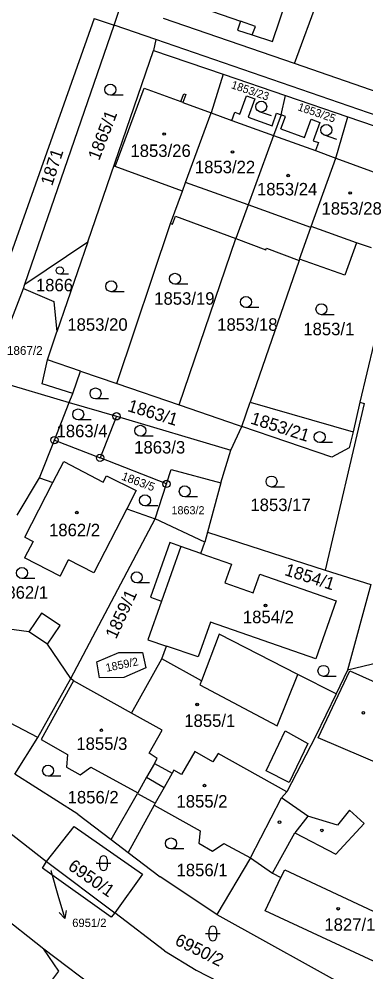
# Model space of a CAD drawing. Extents: x -593183 to -588034, y -1130415 to -1124994.
# Drawn here: x -590455.2 to -590407.9, y -1129215.7 to -1129085.7 of the extents above; entities that cross this region are included whole.
import ezdxf

# ---------------------------------------------------------------- set-up
doc = ezdxf.new("R2010")
doc.units = 0
for name, color, linetype in [('Vrstva 1', 7, 'Continuous'), ('Vrstva 16', 7, 'Continuous'), ('Vrstva 18', 7, 'Continuous'), ('Vrstva 19', 7, 'Continuous'), ('Vrstva 24', 7, 'Continuous'), ('Vrstva 25', 7, 'Continuous'), ('Vrstva 4', 7, 'Continuous')]:
    doc.layers.add(name, color=color, linetype=linetype)

msp = doc.modelspace()

# ---------------------------------------------------------------- linework, layer by layer
at = {"layer": 'Vrstva 1'}
for p, q in [((-590417.69, -1129091.82), (-590414.33, -1129082.68)), ((-590444.97, -1129085.65), (-590459.63, -1129127.02)), ((-590454.41, -1129121.9), (-590442.26, -1129086.59)), ((-590444.97, -1129085.65), (-590442.26, -1129086.59)), ((-590436.59, -1129088.54), (-590442.26, -1129086.59)), ((-590417.69, -1129091.82), (-590435.53, -1129085.66)), ((-590436.59, -1129088.54), (-590436.88, -1129090.02)), ((-590395.82, -1129102.61), (-590436.59, -1129088.54)), ((-590445.83, -1129116.11), (-590436.88, -1129090.02)), ((-590436.88, -1129090.02), (-590427.42, -1129093.26)), ((-590395.13, -1129099.59), (-590417.69, -1129091.82)), ((-590427.42, -1129093.26), (-590429.01, -1129098.55)), ((-590427.42, -1129093.26), (-590418.91, -1129096.18)), ((-590442.11, -1129105.83), (-590438.16, -1129095.16)), ((-590438.16, -1129095.16), (-590433.16, -1129097.01)), ((-590433.16, -1129097.01), (-590432.76, -1129095.93)), ((-590432.76, -1129095.93), (-590432.48, -1129096.03)), ((-590432.48, -1129096.03), (-590432.88, -1129097.12)), ((-590432.88, -1129097.12), (-590429.01, -1129098.55)), ((-590425.14, -1129098.7), (-590424.23, -1129096.2)), ((-590424.23, -1129096.2), (-590423.08, -1129096.62)), ((-590423.08, -1129096.62), (-590423.98, -1129099.12)), ((-590419.5, -1129098.81), (-590418.91, -1129096.18)), ((-590418.91, -1129096.18), (-590410.39, -1129099.1)), ((-590432.52, -1129108.04), (-590429.01, -1129098.55)), ((-590429.01, -1129098.55), (-590426.23, -1129099.56)), ((-590426.23, -1129099.56), (-590425.83, -1129098.45)), ((-590425.83, -1129098.45), (-590425.14, -1129098.7)), ((-590423.98, -1129099.12), (-590420.74, -1129100.29)), ((-590420.74, -1129100.29), (-590420.12, -1129098.58)), ((-590419.5, -1129098.81), (-590420.53, -1129101.62)), ((-590420.12, -1129098.58), (-590419.5, -1129098.81)), ((-590419.54, -1129100.73), (-590418.92, -1129099.02)), ((-590418.92, -1129099.02), (-590419.5, -1129098.81)), ((-590416.3, -1129101.9), (-590415.4, -1129099.4)), ((-590415.4, -1129099.4), (-590414.21, -1129099.83)), ((-590414.21, -1129099.83), (-590415.12, -1129102.33)), ((-590412.05, -1129104.7), (-590410.39, -1129099.1)), ((-590410.39, -1129099.1), (-590402.83, -1129101.7)), ((-590419.54, -1129100.73), (-590416.3, -1129101.9)), ((-590420.53, -1129101.62), (-590423.99, -1129111.1)), ((-590415.12, -1129102.33), (-590414.42, -1129102.58)), ((-590414.42, -1129102.58), (-590414.83, -1129103.69)), ((-590414.83, -1129103.69), (-590412.05, -1129104.7)), ((-590415.39, -1129114.03), (-590412.05, -1129104.7)), ((-590412.05, -1129104.7), (-590403.97, -1129107.67)), ((-590400.88, -1129104.55), (-590408.76, -1129137.99)), ((-590432.96, -1129109.22), (-590442.11, -1129105.83)), ((-590432.96, -1129109.22), (-590432.52, -1129108.04)), ((-590434.59, -1129113.62), (-590432.96, -1129109.22)), ((-590423.99, -1129111.1), (-590425.66, -1129115.69)), ((-590434.3, -1129113.73), (-590433.9, -1129112.64)), ((-590433.9, -1129112.64), (-590425.66, -1129115.69)), ((-590441.89, -1129135.45), (-590434.59, -1129113.62)), ((-590434.59, -1129113.62), (-590434.3, -1129113.73)), ((-590415.44, -1129114.17), (-590415.39, -1129114.03)), ((-590416.98, -1129118.47), (-590415.44, -1129114.17)), ((-590454.41, -1129121.9), (-590445.83, -1129116.11)), ((-590445.83, -1129116.11), (-590450.04, -1129128.4)), ((-590433.38, -1129138.37), (-590425.66, -1129115.69)), ((-590425.66, -1129115.69), (-590421.58, -1129117.2)), ((-590409.21, -1129116.24), (-590410.81, -1129120.68)), ((-590407.2, -1129116.96), (-590409.21, -1129116.24)), ((-590421.58, -1129117.2), (-590421.51, -1129117.01)), ((-590421.51, -1129117.01), (-590417.05, -1129118.66)), ((-590417.05, -1129118.66), (-590423.73, -1129137.98)), ((-590416.98, -1129118.47), (-590417.05, -1129118.66)), ((-590410.81, -1129120.68), (-590416.98, -1129118.47)), ((-590454.62, -1129122.47), (-590454.41, -1129121.9)), ((-590458.36, -1129132.2), (-590454.62, -1129122.47)), ((-590454.62, -1129122.47), (-590450.47, -1129124.24)), ((-590450.47, -1129124.24), (-590450.04, -1129128.4)), ((-590451.35, -1129132.21), (-590450.04, -1129128.4)), ((-590446.83, -1129133.76), (-590451.35, -1129132.21)), ((-590459.53, -1129134.72), (-590448.36, -1129138.02)), ((-590447.88, -1129136.8), (-590446.83, -1129133.76)), ((-590446.83, -1129133.76), (-590441.89, -1129135.45)), ((-590441.89, -1129135.45), (-590433.38, -1129138.37)), ((-590448.36, -1129138.02), (-590447.88, -1129136.8)), ((-590450.39, -1129143.16), (-590448.36, -1129138.02)), ((-590448.36, -1129138.02), (-590441.93, -1129139.92)), ((-590433.38, -1129138.37), (-590425.34, -1129141.13)), ((-590424.87, -1129141.29), (-590423.73, -1129137.98)), ((-590423.73, -1129137.98), (-590409.7, -1129142.02)), ((-590408.19, -1129138.18), (-590413.48, -1129160.88)), ((-590408.76, -1129137.99), (-590409.7, -1129142.02)), ((-590408.76, -1129137.99), (-590408.19, -1129138.18)), ((-590441.93, -1129139.92), (-590444.17, -1129145.58)), ((-590441.93, -1129139.92), (-590426.37, -1129144.52)), ((-590426.37, -1129144.52), (-590424.87, -1129141.29)), ((-590425.34, -1129141.13), (-590424.87, -1129141.29)), ((-590412.57, -1129145.51), (-590424.87, -1129141.29)), ((-590409.7, -1129142.02), (-590410.22, -1129144.21)), ((-590452.42, -1129148.3), (-590450.39, -1129143.16)), ((-590450.39, -1129143.16), (-590444.17, -1129145.58)), ((-590427.72, -1129148.98), (-590426.37, -1129144.52)), ((-590410.22, -1129144.21), (-590412.57, -1129145.51)), ((-590450.59, -1129148.95), (-590449.11, -1129146.08)), ((-590449.11, -1129146.08), (-590443.74, -1129148.89)), ((-590435.12, -1129149.14), (-590444.17, -1129145.58)), ((-590435.12, -1129149.14), (-590434.48, -1129147.17)), ((-590434.48, -1129147.17), (-590427.72, -1129148.98)), ((-590455.45, -1129153.42), (-590452.42, -1129148.3)), ((-590454.42, -1129156.42), (-590450.59, -1129148.95)), ((-590452.42, -1129148.3), (-590450.59, -1129148.95)), ((-590443.74, -1129148.89), (-590443.28, -1129148.02)), ((-590443.28, -1129148.02), (-590439.27, -1129150.05)), ((-590436.68, -1129153.91), (-590435.12, -1129149.14)), ((-590427.72, -1129148.98), (-590429.52, -1129155.74)), ((-590439.27, -1129150.05), (-590440.54, -1129152.53)), ((-590440.54, -1129152.53), (-590445, -1129161.25)), ((-590440.54, -1129152.53), (-590436.68, -1129153.91)), ((-590448.13, -1129175.68), (-590436.68, -1129153.91)), ((-590429.88, -1129157.09), (-590436.68, -1129153.91)), ((-590429.52, -1129155.74), (-590429.88, -1129157.09)), ((-590429.52, -1129155.74), (-590413.48, -1129160.88)), ((-590453.3, -1129157), (-590454.45, -1129159.23)), ((-590454.42, -1129156.42), (-590453.3, -1129157)), ((-590434.68, -1129157.13), (-590437.3, -1129164.59)), ((-590433.17, -1129157.65), (-590434.68, -1129157.13)), ((-590430.44, -1129158.61), (-590433.17, -1129157.65)), ((-590430.44, -1129158.61), (-590429.88, -1129157.09)), ((-590449.6, -1129161.72), (-590454.45, -1129159.23)), ((-590449.6, -1129161.72), (-590448.45, -1129159.49)), ((-590445, -1129161.25), (-590448.45, -1129159.49)), ((-590430.44, -1129158.61), (-590426.28, -1129160.07)), ((-590426.28, -1129160.07), (-590427.18, -1129162.64)), ((-590413.48, -1129160.88), (-590407.29, -1129162.87)), ((-590423.31, -1129163.99), (-590422.41, -1129161.43)), ((-590422.41, -1129161.43), (-590411.98, -1129165.08)), ((-590427.18, -1129162.64), (-590423.31, -1129163.99)), ((-590407.29, -1129162.87), (-590410.48, -1129174.52)), ((-590437.3, -1129164.59), (-590435.78, -1129165.12)), ((-590435.78, -1129165.12), (-590437.64, -1129170.4)), ((-590411.98, -1129165.08), (-590414.77, -1129173.01)), ((-590452.14, -1129166.75), (-590453.87, -1129169.33)), ((-590449.61, -1129168.43), (-590452.14, -1129166.75)), ((-590451.32, -1129171), (-590449.61, -1129168.43)), ((-590429.13, -1129167.97), (-590430.81, -1129172.74)), ((-590414.77, -1129173.01), (-590429.13, -1129167.97)), ((-590453.87, -1129169.33), (-590457.53, -1129168.79)), ((-590427.96, -1129169.64), (-590430.37, -1129175.97)), ((-590417.21, -1129175.12), (-590427.96, -1129169.64)), ((-590390.09, -1129169.62), (-590410.48, -1129174.52)), ((-590448.13, -1129175.68), (-590451.32, -1129171)), ((-590437.64, -1129170.4), (-590435.11, -1129171.27)), ((-590435.74, -1129172.97), (-590435.11, -1129171.27)), ((-590430.81, -1129172.74), (-590435.11, -1129171.27)), ((-590444.63, -1129173.4), (-590441.61, -1129172.13)), ((-590441.61, -1129172.13), (-590438.38, -1129172.13)), ((-590438.38, -1129172.13), (-590437.94, -1129174.23)), ((-590444.23, -1129175.56), (-590444.63, -1129173.4)), ((-590439.89, -1129180.4), (-590435.74, -1129172.97)), ((-590430.37, -1129175.97), (-590435.74, -1129172.97)), ((-590485.36, -1129174.1), (-590451.45, -1129200.65)), ((-590437.94, -1129174.23), (-590440.95, -1129175.53)), ((-590412.02, -1129177.76), (-590417.21, -1129175.12)), ((-590410.48, -1129174.52), (-590412.02, -1129177.76)), ((-590452.66, -1129183.71), (-590448.13, -1129175.68)), ((-590447.79, -1129176), (-590452.19, -1129183.98)), ((-590447.79, -1129176), (-590448.13, -1129175.68)), ((-590439.89, -1129180.4), (-590447.79, -1129176)), ((-590440.95, -1129175.53), (-590444.23, -1129175.56)), ((-590412.02, -1129177.76), (-590414.8, -1129183.6)), ((-590435.73, -1129182.71), (-590439.89, -1129180.4)), ((-590452.66, -1129183.71), (-590457.4, -1129181.23)), ((-590437.48, -1129185.85), (-590435.73, -1129182.71)), ((-590455.78, -1129188.72), (-590452.66, -1129183.71)), ((-590452.19, -1129183.98), (-590448.6, -1129186.02)), ((-590414.8, -1129183.6), (-590418.72, -1129191.13)), ((-590448.6, -1129186.02), (-590448.76, -1129187.76)), ((-590436.38, -1129186.56), (-590437.48, -1129185.85)), ((-590436.77, -1129187.27), (-590436.38, -1129186.56)), ((-590431.27, -1129185.64), (-590433.07, -1129188.77)), ((-590428.79, -1129187.03), (-590431.27, -1129185.64)), ((-590428.1, -1129185.91), (-590428.79, -1129187.03)), ((-590418.72, -1129191.13), (-590428.1, -1129185.91)), ((-590448.76, -1129187.76), (-590446.86, -1129188.83)), ((-590446.86, -1129188.83), (-590445.44, -1129187.77)), ((-590445.44, -1129187.77), (-590439.02, -1129191.28)), ((-590436.77, -1129187.27), (-590437.82, -1129189.14)), ((-590434.14, -1129188.17), (-590434.36, -1129188.57)), ((-590433.07, -1129188.77), (-590434.14, -1129188.17)), ((-590447.21, -1129194.16), (-590455.78, -1129188.72)), ((-590437.82, -1129189.14), (-590439.02, -1129191.28)), ((-590434.36, -1129188.57), (-590435.43, -1129190.53)), ((-590435.43, -1129190.53), (-590436.64, -1129192.68)), ((-590442.65, -1129197.64), (-590439.07, -1129191.37)), ((-590439.02, -1129191.28), (-590439.07, -1129191.37)), ((-590423.69, -1129200.15), (-590419.44, -1129191.96)), ((-590419.44, -1129191.96), (-590418.72, -1129191.13)), ((-590436.78, -1129192.94), (-590440.34, -1129199.4)), ((-590436.64, -1129192.68), (-590436.78, -1129192.94)), ((-590436.78, -1129192.94), (-590430.53, -1129196.46)), ((-590447.21, -1129194.16), (-590442.65, -1129197.64)), ((-590451.45, -1129200.65), (-590447.68, -1129195.84)), ((-590447.68, -1129195.84), (-590438.41, -1129202.37)), ((-590430.53, -1129196.46), (-590430.69, -1129198.13)), ((-590451.81, -1129212.59), (-590470.99, -1129197.54)), ((-590442.65, -1129197.64), (-590440.34, -1129199.4)), ((-590430.69, -1129198.13), (-590428.86, -1129199.21)), ((-590428.86, -1129199.21), (-590427.3, -1129198.18)), ((-590427.3, -1129198.18), (-590423.69, -1129200.15)), ((-590440.34, -1129199.4), (-590435.98, -1129202.73)), ((-590452.03, -1129201.54), (-590451.45, -1129200.65)), ((-590451.45, -1129200.65), (-590442.17, -1129207.63)), ((-590423.69, -1129200.15), (-590428.24, -1129207.87)), ((-590442.65, -1129208.24), (-590452.03, -1129201.54)), ((-590438.41, -1129202.37), (-590442.17, -1129207.63)), ((-590428.24, -1129207.87), (-590435.98, -1129202.73)), ((-590442.17, -1129207.63), (-590442.65, -1129208.24)), ((-590435.37, -1129212.83), (-590442.17, -1129207.63)), ((-590428.24, -1129207.87), (-590403.83, -1129221.39)), ((-590449.79, -1129215.59), (-590451.81, -1129212.59)), ((-590437.47, -1129223.43), (-590451.81, -1129212.59)), ((-590435.37, -1129212.83), (-590431.08, -1129215.43)), ((-590431.08, -1129215.43), (-590412.29, -1129225.07)), ((-590452.4, -1129219.06), (-590449.79, -1129215.59))]:
    msp.add_line(p, q, dxfattribs=at)
at = {"layer": 'Vrstva 16'}
msp.add_line((-590450.89, -1129201.85), (-590449.81, -1129205.54), dxfattribs=at)
at = {"layer": 'Vrstva 24'}
for centre, radius in [((-590441.93, -1129139.92), 0.5), ((-590441.93, -1129139.92), 0.0327), ((-590450.39, -1129143.16), 0.5), ((-590450.39, -1129143.16), 0.0327), ((-590444.17, -1129145.58), 0.5), ((-590444.17, -1129145.58), 0.0327), ((-590435.12, -1129149.14), 0.5), ((-590435.12, -1129149.14), 0.0327)]:
    msp.add_circle(centre, radius, dxfattribs=at)
at = {"layer": 'Vrstva 25'}
for p, q in [((-590441.02, -1129096.13), (-590442.77, -1129096.13)), ((-590420.79, -1129098.96), (-590422.45, -1129098.39)), ((-590411.93, -1129102.16), (-590413.59, -1129101.59)), ((-590448.47, -1129120.54), (-590449.64, -1129120.54)), ((-590432.21, -1129121.91), (-590433.96, -1129121.91)), ((-590440.9, -1129122.93), (-590442.65, -1129122.93)), ((-590422.54, -1129125.08), (-590424.29, -1129125.08)), ((-590412.26, -1129126.06), (-590414.01, -1129126.06)), ((-590443.04, -1129137.55), (-590444.79, -1129137.55)), ((-590445.4, -1129140.41), (-590447.15, -1129140.41)), ((-590436.93, -1129142.64), (-590438.68, -1129142.64)), ((-590412.5, -1129143.5), (-590414.25, -1129143.5)), ((-590419.06, -1129149.56), (-590420.81, -1129149.56)), ((-590430.88, -1129150.9), (-590432.63, -1129150.9)), ((-590436.3, -1129152.12), (-590438.05, -1129152.12)), ((-590453.06, -1129162.03), (-590454.81, -1129162.03)), ((-590437.42, -1129162.62), (-590439.17, -1129162.62)), ((-590411.98, -1129175.38), (-590413.73, -1129175.38)), ((-590449.5, -1129189), (-590451.25, -1129189)), ((-590432.76, -1129198.92), (-590434.51, -1129198.92)), ((-590444.71, -1129200.85), (-590442.71, -1129200.85)), ((-590444.21, -1129201.35), (-590444.21, -1129200.35)), ((-590443.21, -1129200.35), (-590443.21, -1129201.35)), ((-590449.81, -1129205.54), (-590448.96, -1129208.42)), ((-590429.31, -1129210.95), (-590429.31, -1129209.95)), ((-590428.31, -1129209.95), (-590428.31, -1129210.95)), ((-590429.81, -1129210.45), (-590427.81, -1129210.45))]:
    msp.add_line(p, q, dxfattribs=at)
msp.add_lwpolyline([(-590448.77, -1129207.32), (-590448.96, -1129208.42), (-590449.73, -1129207.6)], dxfattribs=at)
for centre, radius in [((-590442.77, -1129095.38), 0.75), ((-590422.21, -1129097.68), 0.75), ((-590413.35, -1129100.88), 0.75), ((-590435.43, -1129101.42), 0.175), ((-590435.43, -1129101.42), 0.15), ((-590426.12, -1129103.87), 0.175), ((-590426.12, -1129103.87), 0.15), ((-590418.54, -1129107.09), 0.175), ((-590418.54, -1129107.09), 0.15), ((-590410.1, -1129109.46), 0.175), ((-590410.1, -1129109.46), 0.15), ((-590449.64, -1129120.04), 0.503), ((-590433.96, -1129121.16), 0.75), ((-590442.65, -1129122.18), 0.75), ((-590424.29, -1129124.33), 0.75), ((-590414.01, -1129125.31), 0.75), ((-590444.79, -1129136.8), 0.75), ((-590447.15, -1129139.66), 0.75), ((-590438.68, -1129141.89), 0.75), ((-590414.25, -1129142.75), 0.75), ((-590420.81, -1129148.81), 0.75), ((-590432.63, -1129150.15), 0.75), ((-590438.05, -1129151.37), 0.75), ((-590447.33, -1129153.05), 0.175), ((-590447.33, -1129153.05), 0.15), ((-590454.81, -1129161.28), 0.75), ((-590439.17, -1129161.87), 0.75), ((-590421.62, -1129165.71), 0.175), ((-590421.62, -1129165.71), 0.15), ((-590413.73, -1129174.63), 0.75), ((-590430.94, -1129179.22), 0.175), ((-590430.94, -1129179.22), 0.15), ((-590408.3, -1129180.36), 0.175), ((-590443.99, -1129182.73), 0.175), ((-590443.99, -1129182.73), 0.15), ((-590451.25, -1129188.25), 0.75), ((-590429.95, -1129190.28), 0.175), ((-590429.95, -1129190.28), 0.15), ((-590419.73, -1129195.27), 0.175), ((-590413.94, -1129196.39), 0.175), ((-590434.51, -1129198.17), 0.75), ((-590411.72, -1129207.07), 0.175), ((-590411.72, -1129207.07), 0.15)]:
    msp.add_circle(centre, radius, dxfattribs=at)
for centre, start, end in [((-590443.71, -1129200.35), 90, 180), ((-590443.71, -1129200.35), 0, 90), ((-590443.71, -1129201.35), 180, 270), ((-590443.71, -1129201.35), 270, 0), ((-590428.81, -1129209.95), 90, 180), ((-590428.81, -1129209.95), 0, 90), ((-590428.81, -1129210.95), 180, 270), ((-590428.81, -1129210.95), 270, 0)]:
    msp.add_arc(centre, 0.5, start, end, dxfattribs=at)
at = {"layer": 'Vrstva 4'}
for p, q in [((-590442.26, -1129086.59), (-590440.19, -1129080.53)), ((-590420.66, -1129088.82), (-590418.68, -1129082.84)), ((-590430.15, -1129084.27), (-590425.03, -1129086.05)), ((-590425.03, -1129086.05), (-590425.45, -1129087.26)), ((-590423.01, -1129086.75), (-590425.03, -1129086.05)), ((-590423.45, -1129087.91), (-590423.01, -1129086.75)), ((-590425.45, -1129087.26), (-590423.45, -1129087.91)), ((-590423.45, -1129087.91), (-590420.66, -1129088.82)), ((-590432.88, -1129097.12), (-590433.16, -1129097.01)), ((-590426.23, -1129099.56), (-590420.53, -1129101.62)), ((-590420.53, -1129101.62), (-590414.83, -1129103.69)), ((-590423.99, -1129111.1), (-590432.52, -1129108.04)), ((-590415.44, -1129114.17), (-590423.99, -1129111.1)), ((-590409.21, -1129116.24), (-590415.39, -1129114.03)), ((-590452.06, -1129135.51), (-590451.35, -1129132.21)), ((-590447.88, -1129136.8), (-590452.06, -1129135.51)), ((-590433.17, -1129157.65), (-590435.78, -1129165.12)), ((-590451.32, -1129171), (-590453.87, -1129169.33)), ((-590420.02, -1129182.13), (-590417.21, -1129175.12)), ((-590414.45, -1129183.77), (-590410.16, -1129174.62)), ((-590410.16, -1129174.62), (-590400.99, -1129178.78)), ((-590430.37, -1129175.97), (-590430.59, -1129176.54)), ((-590430.59, -1129176.54), (-590420.02, -1129182.13)), ((-590421.55, -1129188.28), (-590418.94, -1129182.83)), ((-590418.94, -1129182.83), (-590415.84, -1129184.55)), ((-590405.21, -1129187.72), (-590414.45, -1129183.77)), ((-590415.84, -1129184.55), (-590418.4, -1129189.84)), ((-590436.77, -1129187.27), (-590434.36, -1129188.57)), ((-590437.82, -1129189.14), (-590435.43, -1129190.53)), ((-590418.4, -1129189.84), (-590421.55, -1129188.28)), ((-590439.07, -1129191.37), (-590436.64, -1129192.68)), ((-590415.86, -1129194.43), (-590419.44, -1129191.96)), ((-590415.86, -1129194.43), (-590417.65, -1129196.72)), ((-590411.84, -1129195.66), (-590415.86, -1129194.43)), ((-590410.18, -1129193.63), (-590411.84, -1129195.66)), ((-590408.19, -1129195.46), (-590410.18, -1129193.63)), ((-590412.03, -1129199.61), (-590408.19, -1129195.46)), ((-590420.66, -1129202.21), (-590417.65, -1129196.72)), ((-590417.65, -1129196.72), (-590412.03, -1129199.61)), ((-590423.69, -1129200.15), (-590420.66, -1129202.21)), ((-590420.66, -1129202.21), (-590419.52, -1129202.83)), ((-590419.52, -1129202.83), (-590419.01, -1129201.76)), ((-590419.01, -1129201.76), (-590406.26, -1129207.74)), ((-590421.67, -1129207.34), (-590419.52, -1129202.83)), ((-590403.9, -1129215.64), (-590421.67, -1129207.34))]:
    msp.add_line(p, q, dxfattribs=at)

# ---------------------------------------------------------------- texts
at = {"layer": 'Vrstva 16'}
msp.add_text('6951/2', height=1.14, dxfattribs=at).set_placement((-590447.96, -1129209.56))
at = {"layer": 'Vrstva 18'}
for s, height, rotation, p in [('1853/23', 1.1, 341.087, (-590426.4, -1129095.15)), ('1853/25', 1.1, 341.087, (-590417.33, -1129098.16)), ('1865/1', 1.7, 69.0013, (-590444.29, -1129105.12)), ('1871', 1.7, 72, (-590450.7, -1129108.59)), ('1863/1', 1.7, 342.8788, (-590440.53, -1129139.19)), ('1853/21', 1.7, 342, (-590423.78, -1129140.88)), ('1863/5', 1.14, 339.6224, (-590441.33, -1129148.54)), ('1854/1', 1.7, 342.3064, (-590419.14, -1129161.55)), ('1859/1', 1.7, 65.2868, (-590441.99, -1129170.39)), ('1859/2', 1.1, 11.7251, (-590443.28, -1129174.77)), ('6950/1', 1.7, 325.008, (-590448.67, -1129201.6)), ('6950/2', 1.7, 333.5286, (-590434.11, -1129211.9))]:
    msp.add_text(s, height=height, rotation=rotation, dxfattribs=at).set_placement(p)
for s, height, p in [('1866', 1.7, (-590452.91, -1129122.87)), ('1853/19', 1.7, (-590436.79, -1129124.7)), ('1853/20', 1.7, (-590448.63, -1129128.25)), ('1853/18', 1.7, (-590428.21, -1129128.25)), ('1853/1', 1.7, (-590416.48, -1129128.86)), ('1867/2', 1.19, (-590456.86, -1129131.54)), ('1863/4', 1.7, (-590450.1, -1129142.77)), ('1863/3', 1.7, (-590439.52, -1129144.99)), ('1853/17', 1.7, (-590423.69, -1129152.84)), ('1863/2', 1.1, (-590434.44, -1129153.28)), ('1862/1', 1.7, (-590458.2, -1129164.79)), ('1856/2', 1.7, (-590448.59, -1129192.71)), ('1856/1', 1.7, (-590433.75, -1129202.64)), ('6951/2', 0.1, (-590450.89, -1129201.85))]:
    msp.add_text(s, height=height, dxfattribs=at).set_placement(p)
at = {"layer": 'Vrstva 19'}
for s, p in [('1853/26', (-590440.03, -1129104.55)), ('1853/22', (-590431.25, -1129106.77)), ('1853/24', (-590422.79, -1129109.79)), ('1853/28', (-590414, -1129112.42)), ('1862/2', (-590451.12, -1129156.27)), ('1854/2', (-590424.71, -1129168.13)), ('1855/1', (-590432.7, -1129182.27)), ('1855/3', (-590447.4, -1129185.41)), ('1855/2', (-590433.76, -1129193.27)), ('1827/1', (-590413.61, -1129210.08))]:
    msp.add_text(s, height=1.7, dxfattribs=at).set_placement(p)

doc.saveas('drawing.dxf')
